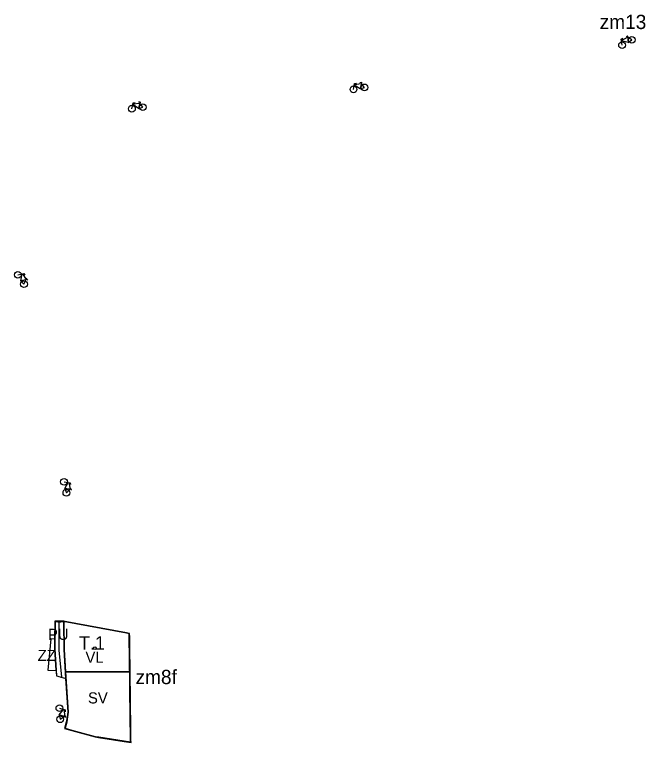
# Model space of a CAD drawing. Extents: x -555070 to -553076, y -1186731 to -1182766.
# Drawn here: x -554193 to -553396, y -1184218 to -1183299 of the extents above; entities that cross this region are included whole.
import ezdxf

# ---------------------------------------------------------------- set-up
doc = ezdxf.new("R2010")
doc.units = 0
for name, color, linetype in [('HRANICE_ZMENY_DO_KOO', 7, 'Continuous'), ('Level 10', 7, 'Continuous'), ('Level 13', 7, 'Continuous'), ('Level 4', 7, 'Continuous'), ('Level 46', 7, 'Continuous'), ('Level 52', 7, 'Continuous'), ('Level 56', 7, 'Continuous'), ('Level 58', 7, 'Continuous'), ('Level 59', 7, 'Continuous'), ('Level 63', 7, 'Continuous'), ('Level 7', 7, 'Continuous'), ('MISTNI_KOMUNIKACE_stav', 7, 'Continuous'), ('OBRYS_PLOCH', 7, 'Continuous'), ('stav_PU', 7, 'Continuous'), ('stav_SV', 7, 'Continuous'), ('stav_ZZ', 7, 'Continuous'), ('ZU_plocha_aktualizace', 7, 'Continuous')]:
    doc.layers.add(name, color=color, linetype=linetype)

msp = doc.modelspace()

# ---------------------------------------------------------------- linework, layer by layer
at = {"layer": 'HRANICE_ZMENY_DO_KOO'}
for p, q in [((-554147.33, -1184087.16), (-554150.8, -1184126.62)), ((-554142.18, -1184087.55), (-554147.33, -1184087.16)), ((-554142.18, -1184087.55), (-554142.18, -1184087.55)), ((-554150.8, -1184126.62), (-554140.46, -1184126.98)), ((-554140.45, -1184127.06), (-554139.99, -1184133.71)), ((-554139.99, -1184133.71), (-554128.13, -1184137.12))]:
    msp.add_line(p, q, dxfattribs=at)
msp.add_lwpolyline([(-554128.63, -1184137.15), (-554125.82, -1184179.53), (-554126.67, -1184185.36), (-554127.67, -1184192.14), (-554129.93, -1184200.04), (-554120.74, -1184202.65), (-554116.07, -1184203.97), (-554091.33, -1184210.68), (-554086.83, -1184211.38), (-554054.52, -1184216.44), (-554045.95, -1184217.8), (-554045.99, -1184214.36), (-554046.75, -1184151.78), (-554046.87, -1184141.37), (-554047.63, -1184084.3), (-554047.69, -1184080.14), (-554051.6, -1184079.42), (-554115.5, -1184067.65), (-554126.97, -1184065.54), (-554130.74, -1184064.84), (-554142.27, -1184064.84), (-554142.37, -1184065.56), (-554142.68, -1184087.56)], dxfattribs=at)
at = {"layer": 'Level 13'}
for p, q in [((-554141.87, -1184065.6), (-554142.18, -1184087.56)), ((-554141.83, -1184065.34), (-554141.87, -1184065.6)), ((-554130.79, -1184065.34), (-554141.83, -1184065.34)), ((-554127.06, -1184066.03), (-554130.79, -1184065.34)), ((-554115.59, -1184068.14), (-554127.06, -1184066.03)), ((-554051.69, -1184079.91), (-554115.59, -1184068.14)), ((-554048.18, -1184080.56), (-554051.69, -1184079.91)), ((-554048.13, -1184084.31), (-554048.18, -1184080.56)), ((-554147.33, -1184087.16), (-554150.8, -1184126.62)), ((-554142.18, -1184087.55), (-554147.33, -1184087.16)), ((-554142.18, -1184087.55), (-554142.18, -1184087.55)), ((-554150.8, -1184126.62), (-554140.46, -1184126.98)), ((-554140.45, -1184127.06), (-554139.99, -1184133.71)), ((-554139.99, -1184133.71), (-554128.13, -1184137.12)), ((-554128.13, -1184137.12), (-554125.32, -1184179.55)), ((-554126.18, -1184185.43), (-554127.18, -1184192.25)), ((-554125.32, -1184179.55), (-554126.18, -1184185.43)), ((-554127.18, -1184192.25), (-554129.31, -1184199.7)), ((-554129.31, -1184199.7), (-554120.6, -1184202.17)), ((-554120.6, -1184202.17), (-554115.94, -1184203.49)), ((-554115.94, -1184203.49), (-554091.23, -1184210.19)), ((-554091.23, -1184210.19), (-554088.11, -1184210.68)), ((-554088.11, -1184210.68), (-554086.75, -1184210.89)), ((-554086.75, -1184210.89), (-554054.44, -1184215.95)), ((-554046.46, -1184217.21), (-554046.49, -1184214.37)), ((-554054.44, -1184215.95), (-554046.46, -1184217.21))]:
    msp.add_line(p, q, dxfattribs=at)
msp.add_lwpolyline([(-554046.49, -1184214.37), (-554047.25, -1184151.79), (-554047.37, -1184141.38), (-554048.13, -1184084.31)], dxfattribs=at)
at = {"layer": 'Level 4'}
msp.add_circle((-554091.58, -1184098.7), 1.64, dxfattribs=at)
at = {"layer": 'Level 52'}
msp.add_lwpolyline([(-554130.79, -1184065.34), (-554141.83, -1184065.34), (-554141.99, -1184074.35), (-554142.18, -1184087.55), (-554142.35, -1184099.82), (-554142.27, -1184100.97), (-554140.46, -1184126.98), (-554139.99, -1184133.71)], dxfattribs=at)
at = {"layer": 'Level 56'}
for p, q in [((-554130.79, -1184065.34), (-554130.94, -1184066.61)), ((-554130.94, -1184066.61), (-554130.56, -1184100.41)), ((-554127.06, -1184066.03), (-554130.79, -1184065.34)), ((-554115.59, -1184068.14), (-554127.06, -1184066.03)), ((-554051.69, -1184079.91), (-554115.59, -1184068.14)), ((-554048.18, -1184080.56), (-554051.69, -1184079.91)), ((-554048.13, -1184084.31), (-554048.18, -1184080.56)), ((-554047.56, -1184127.43), (-554048.13, -1184084.31)), ((-554130.56, -1184100.41), (-554128.7, -1184128.51)), ((-554128.7, -1184128.51), (-554047.54, -1184128.51)), ((-554047.54, -1184128.51), (-554047.56, -1184127.43))]:
    msp.add_line(p, q, dxfattribs=at)
at = {"layer": 'Level 58'}
for p, q in [((-553426.89, -1183329.92), (-553424.72, -1183328.8)), ((-553425.8, -1183337.48), (-553426.89, -1183329.92)), ((-553426.69, -1183331.41), (-553418.95, -1183327.53)), ((-553418.06, -1183334.3), (-553426.58, -1183332.11)), ((-553419.13, -1183326.16), (-553420.74, -1183327.01)), ((-553419.13, -1183326.16), (-553418.24, -1183325.72)), ((-553419.13, -1183326.16), (-553418.06, -1183334.3)), ((-553413.52, -1183330.78), (-553418.95, -1183327.53)), ((-553418.06, -1183334.3), (-553413.52, -1183330.78)), ((-553764.93, -1183393.24), (-553763.55, -1183385.73)), ((-553756.57, -1183392.7), (-553763.95, -1183387.91)), ((-553763.83, -1183387.2), (-553755.26, -1183386)), ((-553763.55, -1183385.73), (-553761.13, -1183385.36)), ((-553754.99, -1183384.65), (-553756.78, -1183384.94)), ((-553754.99, -1183384.65), (-553756.57, -1183392.7)), ((-553751.15, -1183390.81), (-553755.26, -1183386)), ((-553754.99, -1183384.65), (-553754, -1183384.51)), ((-553756.57, -1183392.7), (-553751.15, -1183390.81)), ((-554044.82, -1183417.67), (-554043.21, -1183410.21)), ((-554036.45, -1183417.39), (-554043.68, -1183412.37)), ((-554043.53, -1183411.67), (-554034.93, -1183410.73)), ((-554043.21, -1183410.21), (-554040.78, -1183409.91)), ((-554034.62, -1183409.4), (-554036.45, -1183417.39)), ((-554036.45, -1183417.39), (-554030.97, -1183415.68)), ((-554034.62, -1183409.4), (-554036.42, -1183409.63)), ((-554030.97, -1183415.68), (-554034.93, -1183410.73)), ((-554034.62, -1183409.4), (-554033.63, -1183409.29)), ((-554188.78, -1183627.48), (-554181.33, -1183625.79)), ((-554184.99, -1183634.95), (-554183.49, -1183626.28)), ((-554182.79, -1183626.12), (-554178.31, -1183633.52)), ((-554181.33, -1183625.79), (-554180.04, -1183627.87)), ((-554176.96, -1183633.23), (-554184.99, -1183634.95)), ((-554184.99, -1183634.95), (-554181.11, -1183639.19)), ((-554181.11, -1183639.19), (-554178.31, -1183633.52)), ((-554176.96, -1183633.23), (-554177.94, -1183631.7)), ((-554176.96, -1183633.23), (-554176.45, -1183634.09)), ((-554130.55, -1183888.83), (-554122.99, -1183889.91)), ((-554129.68, -1183897.15), (-554125.18, -1183889.59)), ((-554124.47, -1183889.69), (-554122.93, -1183898.2)), ((-554122.99, -1183889.91), (-554122.52, -1183892.31)), ((-554121.57, -1183898.42), (-554129.68, -1183897.15)), ((-554129.68, -1183897.15), (-554127.58, -1183902.5)), ((-554127.58, -1183902.5), (-554122.93, -1183898.2)), ((-554121.57, -1183898.42), (-554121.93, -1183896.64)), ((-554121.57, -1183898.42), (-554121.4, -1183899.4)), ((-554136.68, -1184182.91), (-554131.16, -1184176.06)), ((-554136.37, -1184174.54), (-554129.04, -1184176.68)), ((-554130.48, -1184176.26), (-554130.15, -1184184.9)), ((-554129.04, -1184176.68), (-554128.92, -1184179.12)), ((-554128.83, -1184185.31), (-554136.68, -1184182.91)), ((-554136.68, -1184182.91), (-554135.36, -1184188.5)), ((-554135.36, -1184188.5), (-554130.15, -1184184.9)), ((-554128.83, -1184185.31), (-554128.94, -1184183.49)), ((-554128.83, -1184185.31), (-554128.8, -1184186.3))]:
    msp.add_line(p, q, dxfattribs=at)
for centre in [(-553425.8, -1183337.48), (-553413.52, -1183330.78), (-553751.15, -1183390.81), (-553764.93, -1183393.24), (-554044.82, -1183417.67), (-554030.97, -1183415.68), (-554188.78, -1183627.48), (-554181.12, -1183639.19), (-554130.55, -1183888.83), (-554127.58, -1183902.5), (-554136.37, -1184174.54), (-554135.36, -1184188.5)]:
    msp.add_circle(centre, 4.25, dxfattribs=at)
at = {"layer": 'Level 7'}
for p, q in [((-554130.79, -1184065.34), (-554130.94, -1184066.61)), ((-554130.94, -1184066.61), (-554130.56, -1184100.41)), ((-554127.06, -1184066.03), (-554130.79, -1184065.34)), ((-554115.59, -1184068.14), (-554127.06, -1184066.03)), ((-554051.69, -1184079.91), (-554115.59, -1184068.14)), ((-554048.18, -1184080.56), (-554051.69, -1184079.91)), ((-554048.13, -1184084.31), (-554048.18, -1184080.56)), ((-554047.56, -1184127.43), (-554048.13, -1184084.31)), ((-554130.56, -1184100.41), (-554128.7, -1184128.51)), ((-554128.7, -1184128.51), (-554047.54, -1184128.51)), ((-554047.54, -1184128.51), (-554047.56, -1184127.43))]:
    msp.add_line(p, q, dxfattribs=at)
at = {"layer": 'MISTNI_KOMUNIKACE_stav'}
msp.add_lwpolyline([(-554133.49, -1184135.27), (-554136.83, -1184101.28), (-554136.83, -1184066.06), (-554136.83, -1184065.2)], dxfattribs=at)
at = {"layer": 'OBRYS_PLOCH'}
for p, q in [((-554141.87, -1184065.6), (-554142.35, -1184099.82)), ((-554141.83, -1184065.34), (-554141.87, -1184065.6)), ((-554130.79, -1184065.34), (-554141.83, -1184065.34)), ((-554130.94, -1184066.61), (-554130.79, -1184065.34)), ((-554130.79, -1184065.34), (-554130.94, -1184066.61)), ((-554130.56, -1184100.41), (-554130.94, -1184066.61)), ((-554130.94, -1184066.61), (-554130.56, -1184100.41)), ((-554127.06, -1184066.03), (-554130.79, -1184065.34)), ((-554115.59, -1184068.14), (-554127.06, -1184066.03)), ((-554051.69, -1184079.91), (-554115.59, -1184068.14)), ((-554048.18, -1184080.56), (-554051.69, -1184079.91)), ((-554048.13, -1184084.31), (-554048.18, -1184080.56)), ((-554047.56, -1184127.43), (-554048.13, -1184084.31)), ((-554147.33, -1184087.16), (-554150.8, -1184126.62)), ((-554142.18, -1184087.55), (-554147.33, -1184087.16)), ((-554142.35, -1184099.82), (-554142.18, -1184087.55)), ((-554140.46, -1184126.98), (-554142.35, -1184099.82)), ((-554142.35, -1184099.82), (-554139.99, -1184133.71)), ((-554128.13, -1184137.12), (-554130.56, -1184100.41)), ((-554130.56, -1184100.41), (-554128.7, -1184128.51)), ((-554150.8, -1184126.62), (-554140.46, -1184126.98)), ((-554128.7, -1184128.51), (-554047.54, -1184128.51)), ((-554128.7, -1184128.51), (-554125.32, -1184179.55)), ((-554047.54, -1184128.51), (-554128.7, -1184128.51)), ((-554047.54, -1184128.51), (-554047.56, -1184127.43)), ((-554139.99, -1184133.71), (-554128.13, -1184137.12)), ((-554126.18, -1184185.43), (-554127.18, -1184192.25)), ((-554125.32, -1184179.55), (-554126.18, -1184185.43)), ((-554127.18, -1184192.25), (-554129.31, -1184199.7)), ((-554129.31, -1184199.7), (-554120.6, -1184202.17)), ((-554120.6, -1184202.17), (-554115.94, -1184203.49)), ((-554115.94, -1184203.49), (-554091.23, -1184210.19)), ((-554091.23, -1184210.19), (-554088.11, -1184210.68)), ((-554088.11, -1184210.68), (-554086.75, -1184210.89)), ((-554086.75, -1184210.89), (-554054.44, -1184215.95)), ((-554046.46, -1184217.21), (-554046.49, -1184214.37)), ((-554054.44, -1184215.95), (-554046.46, -1184217.21))]:
    msp.add_line(p, q, dxfattribs=at)
msp.add_lwpolyline([(-554046.49, -1184214.37), (-554047.25, -1184151.79), (-554047.37, -1184141.38), (-554047.54, -1184128.51)], dxfattribs=at)
at = {"layer": 'stav_PU'}
for p, q in [((-554141.87, -1184065.6), (-554142.35, -1184099.82)), ((-554141.83, -1184065.34), (-554141.87, -1184065.6)), ((-554130.79, -1184065.34), (-554141.83, -1184065.34)), ((-554130.94, -1184066.61), (-554130.79, -1184065.34)), ((-554130.56, -1184100.41), (-554130.94, -1184066.61)), ((-554142.35, -1184099.82), (-554139.99, -1184133.71)), ((-554128.13, -1184137.12), (-554130.56, -1184100.41)), ((-554139.99, -1184133.71), (-554128.13, -1184137.12))]:
    msp.add_line(p, q, dxfattribs=at)
at = {"layer": 'stav_SV'}
for p, q in [((-554128.7, -1184128.51), (-554125.32, -1184179.55)), ((-554047.54, -1184128.51), (-554128.7, -1184128.51)), ((-554126.18, -1184185.43), (-554127.18, -1184192.25)), ((-554125.32, -1184179.55), (-554126.18, -1184185.43)), ((-554127.18, -1184192.25), (-554129.31, -1184199.7)), ((-554129.31, -1184199.7), (-554120.6, -1184202.17)), ((-554120.6, -1184202.17), (-554115.94, -1184203.49)), ((-554115.94, -1184203.49), (-554091.23, -1184210.19)), ((-554091.23, -1184210.19), (-554088.11, -1184210.68)), ((-554088.11, -1184210.68), (-554086.75, -1184210.89)), ((-554086.75, -1184210.89), (-554054.44, -1184215.95)), ((-554046.46, -1184217.21), (-554046.49, -1184214.37)), ((-554054.44, -1184215.95), (-554046.46, -1184217.21))]:
    msp.add_line(p, q, dxfattribs=at)
msp.add_lwpolyline([(-554046.49, -1184214.37), (-554047.25, -1184151.79), (-554047.37, -1184141.38), (-554047.54, -1184128.51)], dxfattribs=at)
at = {"layer": 'stav_ZZ'}
for p, q in [((-554147.33, -1184087.16), (-554150.8, -1184126.62)), ((-554142.18, -1184087.55), (-554147.33, -1184087.16)), ((-554142.35, -1184099.82), (-554142.18, -1184087.55)), ((-554140.46, -1184126.98), (-554142.35, -1184099.82)), ((-554150.8, -1184126.62), (-554140.46, -1184126.98))]:
    msp.add_line(p, q, dxfattribs=at)
at = {"layer": 'ZU_plocha_aktualizace'}
for p, q in [((-554138.5, -1184065.34), (-554134.53, -1184065.34)), ((-554134.53, -1184065.34), (-554138.5, -1184065.34)), ((-554130.79, -1184065.34), (-554134.53, -1184065.34)), ((-554141.99, -1184074.35), (-554142.18, -1184087.55)), ((-554142.18, -1184087.55), (-554142.35, -1184099.82)), ((-554142.35, -1184099.82), (-554140.46, -1184126.98)), ((-554128.13, -1184137.12), (-554130.56, -1184100.41)), ((-554140.46, -1184126.98), (-554140.28, -1184129.45)), ((-554140.28, -1184129.45), (-554139.99, -1184133.71)), ((-554139.99, -1184133.71), (-554135.44, -1184135.01)), ((-554134.39, -1184135.32), (-554134.39, -1184135.32)), ((-554134.39, -1184135.32), (-554130.69, -1184136.38)), ((-554130.69, -1184136.38), (-554128.13, -1184137.12))]:
    msp.add_line(p, q, dxfattribs=at)
for points in [[(-554138.5, -1184065.34), (-554141.83, -1184065.34), (-554141.99, -1184074.35)], [(-554130.56, -1184100.41), (-554130.94, -1184066.61), (-554130.79, -1184065.34)], [(-554135.44, -1184135.01), (-554135.44, -1184135.01), (-554134.39, -1184135.32)]]:
    msp.add_lwpolyline(points, dxfattribs=at)

# ---------------------------------------------------------------- texts
at = {"layer": 'Level 10'}
for s, p in [('zm13', (-553454.06, -1183317.09)), ('zm8f', (-554040.26, -1184144.16))]:
    msp.add_text(s, height=18, dxfattribs=at).set_placement(p)
at = {"layer": 'Level 46'}
msp.add_text('T.1', height=17, dxfattribs=at).set_placement((-554111.66, -1184100.7))
at = {"layer": 'Level 59'}
for s, p in [('PU', (-554150.8, -1184088.35)), ('ZZ', (-554163.9, -1184114.97)), ('SV', (-554100.3, -1184168.57))]:
    msp.add_text(s, height=14, dxfattribs=at).set_placement(p)
at = {"layer": 'Level 63'}
msp.add_text('VL', height=14, dxfattribs=at).set_placement((-554103.47, -1184117.22))

doc.saveas('drawing.dxf')
